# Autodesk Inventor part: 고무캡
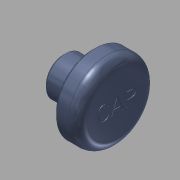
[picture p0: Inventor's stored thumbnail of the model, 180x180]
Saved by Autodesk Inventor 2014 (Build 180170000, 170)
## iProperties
Created: 2017-06
Part Number: 고무캡
Material: 고무
Document SubType Name: Modeling
Designer: mduedu
Density: 1 g/cm^3
Appearance: Rubber - Blue - Version 1.1
Author: mduedu
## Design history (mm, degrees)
sketch "스케치1"
  geometry: L1 (0, 0)-(11, 0); L2 (11, 0)-(11, 8); L3 (11, 8)-(6.5, 8); L4 (0, 4)-(0, 0); L5 (0, 4)-(6, 4); L6 (6, 4)-(6, 7.5); L7 (6, 7.5)-(6.5, 7.5); L8 (6.5, 7.5)-(6.5, 8)
  constraints: 16 end point, 2 horizontal, 2 parallel, 2 perpendicular, 2 point on line, 1 vertical
  dimensions: "d0" = 16 diameter of L3 L1; "d2" = 8 diameter of L5 L1; "d6" = 5 distance between parallel lines of L2 L6; "d7" = 0.5 distance between parallel lines of L8 L6; "d8" = 15 diameter of L7 L1; "d9" = 6 distance between parallel lines of L6 L4
revolve "회전1" sketch "스케치1" stored, may be unused: angle "d10" = 90 deg
hole "구멍1" diameter "d22" = 5; stored, may be unused: countersink angle "d26" = 90 deg, drill point angle "d28" = 0 deg; dims "d23" = 6, "d24" = 4, "d25" = 2, "d27" = 6, "d30" = 10, "d31" = 10
chamfer "모따기1" distance "d13" = 0.5; stored, may be unused: second distance "d14" = 2, angle "d15" = 45 deg
fillet "모깎기3" dims "d29" = 1
fillet "모깎기1" dims "d16" = 0.1
fillet "모깎기2" dims "d17" = 2
sketch "스케치3"
  geometry: 2 further points
  constraints: 1 coincident, 1 other
feature "엠보싱1" sketch "스케치3" dims "d18" = 0.2, "d19" = 0
node "솔리드1"
